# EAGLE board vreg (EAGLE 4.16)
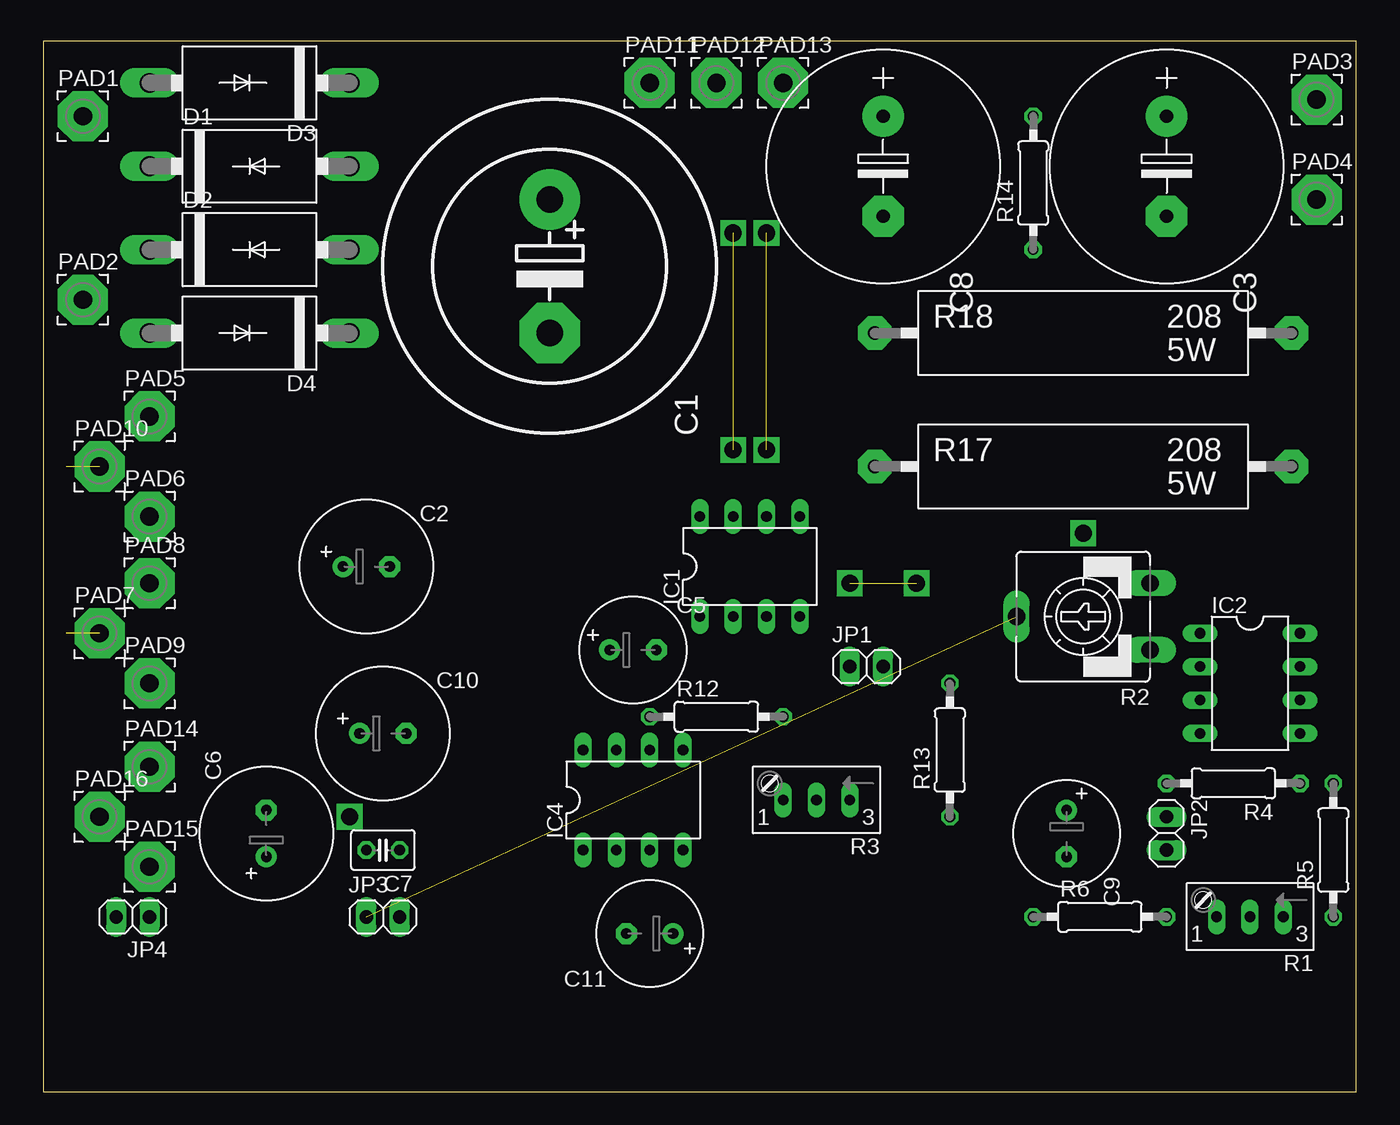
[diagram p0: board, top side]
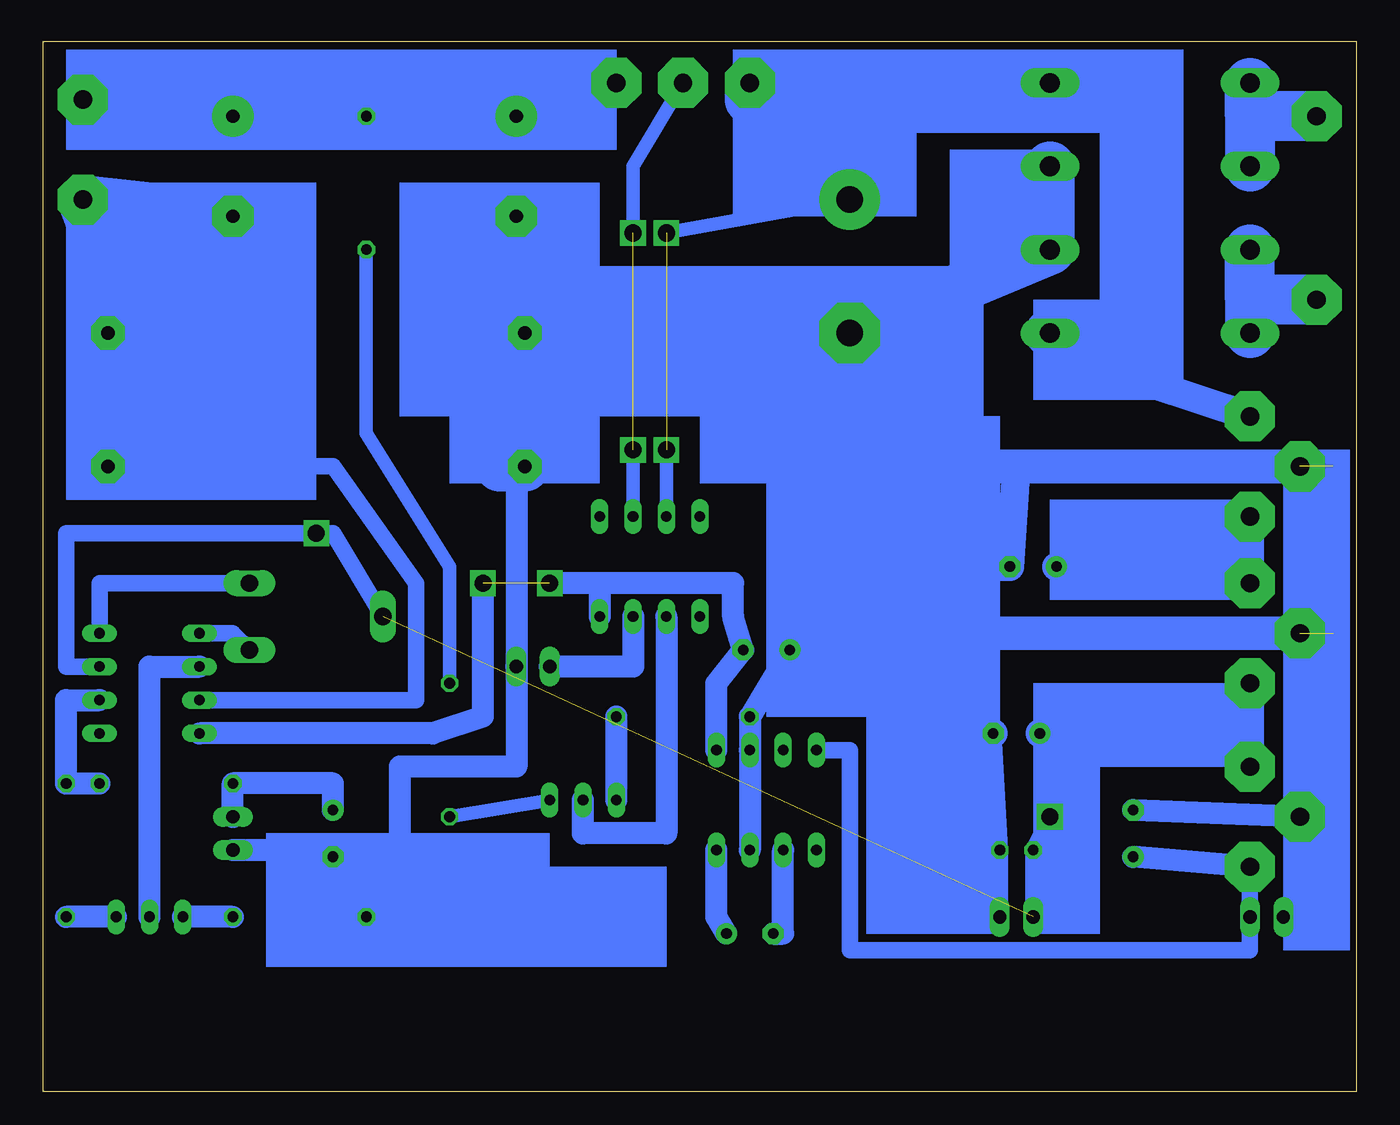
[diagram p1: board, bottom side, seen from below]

Size 100 x 80 mm. Coordinates in mm from the lower left corner, seen from the top.
Outline: 0,0 100,0 100,80 0,80 0,0
Copper layers (1*16): Top 0.035mm / dielectric 1.5mm / Bottom 0.035mm
Design rules "default": minimum track width 10mil, minimum drill 24mil, track to track 8mil, track to pad 8mil, pad to pad 8mil, via to via 8mil, smd to smd 8mil, copper to edge 40mil, drill to drill 8mil, minimum pad ring 10mil, minimum via ring 8mil, stop-mask expansion 4mil, vias tented up to drill 0mil, thermal gap 10mil

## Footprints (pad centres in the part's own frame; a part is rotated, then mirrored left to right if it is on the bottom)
EB25D = drill 2.007 pad 4.597 round: + -5.08,0 | drill 2.007 pad 4.597 octagon: - 5.08,0
E3,5-10 = drill 0.813 pad 1.6 round: + -1.778,0 | drill 0.813 pad 1.6 octagon: - 1.778,0
E7,5-18 = drill 1.016 pad 3.15 round: + -3.81,0 | drill 1.016 pad 3.15 octagon: - 3.81,0
E3,5-8 = drill 0.813 pad 1.6 round: + -1.778,0 | drill 0.813 pad 1.6 octagon: - 1.778,0
C025-030X050 = drill 0.813 octagon: 1 -1.27,0; 2 1.27,0
DO201-15 = drill 1.499 long: A 7.62,0; C -7.62,0
DIL08 = drill 0.813 long: 1 -3.81,-3.81; 2 -1.27,-3.81; 3 1.27,-3.81; 4 3.81,-3.81; 5 3.81,3.81; 6 1.27,3.81; 7 -1.27,3.81; 8 -3.81,3.81
1X02 = drill 1.016 long: 1 -1.27,0; 2 1.27,0
3,81/1,4 = drill 1.397 pad 3.81 octagon: 1 0,0
S64W = drill 0.813 long: A 2.54,1.27; E -2.54,1.27; S 0,1.27
CA9V = drill 1.321 long: A -2.54,-5.08; E 2.54,-5.08; S 0,5.08
0207/10 = drill 0.813 octagon: 1 -5.08,0; 2 5.08,0
KH208-8 = drill 1.016 pad 2.54 octagon: 1 -15.875,0; 2 15.875,0

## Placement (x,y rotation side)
C1  4700uF 50V  [EB25D]  38.57,62.86 270 top
C2  10uF 50V  [E3,5-10]  24.6,40 0 top
C3  100uF 50V  [E7,5-18]  85.56,70.48 270 top
C5  50uF 10v  [E3,5-8]  44.92,33.65 0 top
C6  10uF 50V  [E3,5-10]  16.98,19.68 90 top
C7  0.1uF  [C025-030X050]  25.87,18.41 180 top
C8  100uF 50V  [E7,5-18]  63.97,70.48 270 top
C9  1uF 10v  [E3,5-8]  77.94,19.68 270 top
C10  10uF 50V  [E3,5-10]  25.87,27.3 0 top
C11  50uF 10v  [E3,5-8]  46.19,12.06 180 top
D1  FR307  [DO201-15]  15.71,70.48 0 top
D2  FR307  [DO201-15]  15.71,64.13 0 top
D3  FR307  [DO201-15]  15.71,76.83 180 top
D4  FR307  [DO201-15]  15.71,57.78 180 top
IC1  OP07EQ  [DIL08]  53.81,40 0 top
IC2  OP07EQ  [DIL08]  91.91,31.11 270 top
IC4  MAX660CPA  [DIL08]  44.92,22.22 0 top
JP1  [1X02]  62.7,32.38 0 top
JP2  [1X02]  85.56,19.68 270 top
JP3  [1X02]  25.87,13.33 0 top
JP4  [1X02]  6.82,13.33 180 top
PAD1  [3,81/1,4]  3.01,74.29 0 top
PAD2  [3,81/1,4]  3.01,60.32 0 top
PAD3  [3,81/1,4]  96.99,75.56 0 top
PAD4  [3,81/1,4]  96.99,67.94 0 top
PAD5  [3,81/1,4]  8.09,51.43 0 top
PAD6  [3,81/1,4]  8.09,43.81 0 top
PAD7  [3,81/1,4]  4.28,34.92 0 top
PAD8  [3,81/1,4]  8.09,38.73 0 top
PAD9  [3,81/1,4]  8.09,31.11 0 top
PAD10  [3,81/1,4]  4.28,47.62 0 top
PAD11  [3,81/1,4]  46.19,76.83 0 top
PAD12  [3,81/1,4]  51.27,76.83 0 top
PAD13  [3,81/1,4]  56.35,76.83 0 top
PAD14  [3,81/1,4]  8.09,24.76 0 top
PAD15  [3,81/1,4]  8.09,17.14 0 top
PAD16  [3,81/1,4]  4.28,20.95 0 top
R1  100  [S64W]  91.91,14.6 180 top
R2  100k  [CA9V]  79.21,36.19 90 top
R3  100  [S64W]  58.89,23.49 180 top
R4  2.7k  [0207/10]  90.64,23.49 180 top
R5  10k  [0207/10]  98.26,18.41 90 top
R6  200  [0207/10]  80.48,13.33 0 top
R12  2.7k  [0207/10]  51.27,28.57 0 top
R13  10k  [0207/10]  69.05,26.03 90 top
R14  1.2k*  [0207/10]  75.4,69.21 90 top
R17  0.1  [KH208-8]  79.21,47.62 0 top
R18  0.1  [KH208-8]  79.21,57.78 0 top

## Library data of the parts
C1-C3 C5-C11 R4-R6 R12-R14 = rcl
D1-D4 = diode
IC1 IC2 = linear
IC4 = maxim
JP1-JP4 = pinhead
PAD1-PAD16 = wirepad
R1-R3 = pot
R17 R18 = resistor-power

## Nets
GND: C1.- C2.- C5.+ C6.- C7.1 C8.- C9.- C10.- D1.A D2.A IC4.3 IC4.6 JP1.2 JP2.2 JP3.2 JP4.2 PAD7.1 PAD10.1 PAD16.1 R6.1 R12.1 R17.1 R18.1
N$1: R1.A R6.2
N$2: IC2.2 R1.S
N$3: IC1.2 R3.S
N$4: C9.+ JP2.1 R4.2
N$5: R1.E R5.1
N$6: D1.C D3.A PAD1.1
N$8: D2.C D4.A PAD2.1
N$9: R3.A R12.2
N$10: R3.E R13.1
N$11: C2.+ PAD6.1 PAD8.1
N$13: R13.2 R14.1
N$14: C3.- IC2.3 PAD4.1 R17.2 R18.2
N$15: C11.- IC4.2
N$16: C3.+ C8.+ PAD3.1 PAD13.1 R14.2
N$17: C11.+ IC4.4
N$18: IC1.6 PAD12.1
N$21: IC1.3 JP1.1
N$22: C1.+ D3.C D4.C IC1.7 PAD5.1 PAD11.1
N$25: C6.+ IC4.8 JP4.1 PAD15.1
N$26: IC2.1 R2.A
N$27: IC2.8 R2.E
N$28: C7.2 C10.+ IC2.7 JP3.1 PAD9.1 PAD14.1 R2.S
N$39: IC2.6 R4.1 R5.2
OUT: C5.- IC1.4 IC2.4 IC4.5

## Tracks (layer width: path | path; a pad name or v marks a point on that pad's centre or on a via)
GND  (2 unrouted)
  Bottom 1.27: JP4.2 1.74,13.33 1.74,20.95 | C10.- C7.1 JP3.2
  Bottom 1.676: PAD16.1 C6.- | IC4.3 IC4.6 R12.1 C5.+ 41.11,33.65 38.57,40 | 75.38,18.16 72.86,18.41 72.86,24.76 63.97,24.76 JP1.2 63.97,47.62 | 75.38,18.16 C9.- 81.75,18.41 JP2.2 | 75.38,18.16 75.4,18.41 R6.1
  Bottom 2.184: 1.74,47.62 1.74,34.92 1.74,20.95 PAD16.1 | 28.41,40 C2.- 25.87,47.62 PAD10.1 | 28.41,40 38.57,40 C1.- | C10.- 28.41,27.3 28.41,40
  Bottom 3.81: D1.A D2.A C1.- 65.24,57.78 | R17.1 63.97,47.62 65.24,47.62 65.24,57.78 | 65.24,57.78 R18.1 C8.-
N$1
  Bottom 1.676: R6.2 R1.A
N$2
  Bottom 1.676: R1.S 91.91,32.38 IC2.2
N$3
  Bottom 1.676: IC1.2 52.54,19.68 58.89,19.68 R3.S
N$4
  Bottom 1.676: C9.+ 77.94,23.49 R4.2 JP2.1
N$5
  Bottom 1.676: R1.E R5.1
N$6
  Bottom 3.81: 8.09,74.29 D1.C | 8.09,74.29 D3.A | PAD1.1 8.09,74.29
N$7  (via drill 1.3)
  other vias: 52.54,65.4
N$8
  Bottom 3.81: 8.09,60.32 D4.A | 8.09,60.32 D2.C | PAD2.1 8.09,60.32
N$9
  Bottom 1.676: R3.A R12.2
N$10
  Bottom 1.016: R3.E R13.1
N$11
  Bottom 2.184: PAD8.1 8.09,40 | 8.09,40 PAD6.1 | 8.09,40 C2.+
N$12  (via drill 1.3)
  other vias: 55.08,48.89
N$13
  Bottom 1.016: R14.1 75.4,50.16 69.05,40 R13.2
N$14
  Bottom 1.27: IC2.3 71.59,29.84 71.59,38.73 77.94,47.62 93.18,47.62
  Bottom 3.81: C3.- PAD4.1 93.18,57.78 | R17.2 93.18,47.62 93.18,57.78 | 93.18,57.78 R18.2
N$15
  Bottom 1.676: IC4.2 43.65,12.06 C11.-
N$16
  Bottom 3.81: PAD13.1 C8.+ R14.2 C3.+ PAD3.1
N$17
  Bottom 1.676: IC4.4 48.73,13.33 C11.+
N$18  (1 unrouted)
  Bottom 1.016: PAD12.1 55.08,70.48 55.08,65.4 | IC1.6 55.08,48.89
N$19  (via drill 1.3)
  other vias: 55.08,65.4
N$20  (via drill 1.3)
  other vias: 52.54,48.89
N$21
  Bottom 1.676: IC1.3 55.08,32.38 JP1.1
N$22  (1 unrouted)
  Bottom 1.016: IC1.7 52.54,48.89 | C1.+ 52.54,65.4
  Bottom 2.184: PAD5.1 15.71,53.97 15.71,57.78
  Bottom 3.81: D4.C 15.71,57.78 15.71,76.83 D3.C 33.49,76.83 C1.+ 46.19,75.56 PAD11.1
N$23  (via drill 1.3)
  other vias: 23.33,20.95
N$24  (via drill 1.3)
  other vias: 79.21,42.54
N$25
  Bottom 1.27: PAD15.1 JP4.1 8.09,10.79 38.57,10.79 38.57,26.03 IC4.8
  Bottom 1.676: PAD15.1 C6.+
N$26
  Bottom 1.27: IC2.1 85.56,34.92 R2.A
N$27
  Bottom 1.27: IC2.8 95.72,38.73 R2.E 83.02,38.73
N$28  (1 unrouted)
  Bottom 1.27: C10.+ 23.33,22.22 23.33,20.95 C7.2 JP3.1 | IC2.7 98.26,32.38 98.26,42.54 77.94,42.54 R2.S
  Bottom 2.184: 8.09,27.3 C10.+ | 8.09,27.3 PAD9.1 | PAD14.1 8.09,27.3
N$29  (via drill 1.3)
  other vias: 61.43,38.73
N$30  (via drill 1.3)
  other vias: 66.51,38.73
N$39
  Bottom 1.676: IC2.6 98.26,29.84 R5.2 96.99,23.49 R4.1
OUT  (1 unrouted)
  Bottom 1.676: IC4.5 48.73,31.11 C5.- 47.46,36.19 47.46,38.73 57.62,38.73 | 57.62,38.73 IC1.4 | IC2.4 70.32,27.3 66.51,28.57 66.51,38.73 | 57.62,38.73 61.43,38.73
(copper drawn outside any net)
  shapes: Bottom area x23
